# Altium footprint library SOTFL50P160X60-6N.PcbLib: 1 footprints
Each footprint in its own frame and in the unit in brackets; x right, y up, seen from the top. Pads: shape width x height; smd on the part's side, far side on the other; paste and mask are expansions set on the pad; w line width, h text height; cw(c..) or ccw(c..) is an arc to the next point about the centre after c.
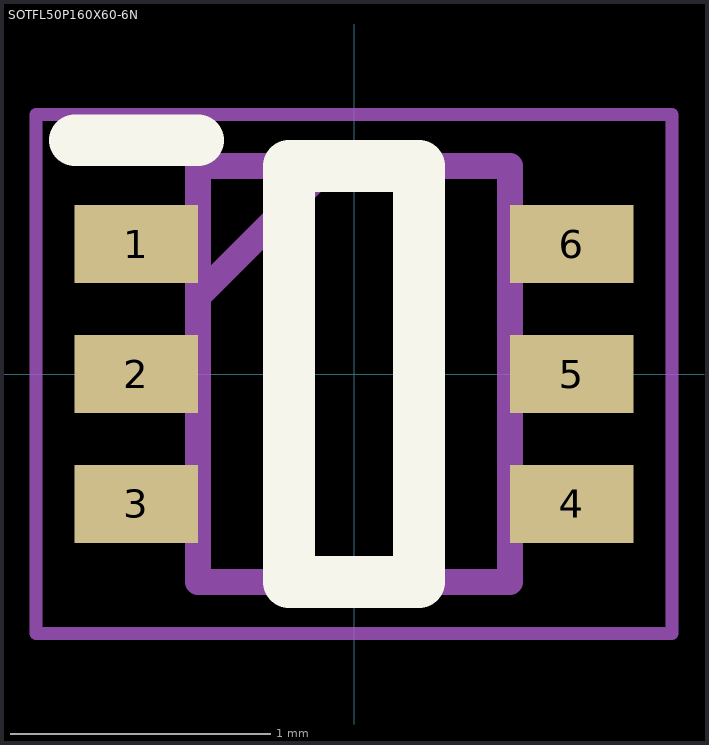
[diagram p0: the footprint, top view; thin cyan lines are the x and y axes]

## SOTFL50P160X60-6N [mm]
pads (6):
  rect 0.475x0.3 smd: 1(-0.838,0.5) 2(-0.838,0) 3(-0.838,-0.5) 4(0.838,-0.5) 5(0.838,0) 6(0.838,0.5)
Top Overlay:
  lines w0.2: -1.075,0.9 -0.6,0.9 ; -0.25,-0.8 0.25,-0.8 0.25,0.8 -0.25,0.8 -0.25,-0.8
Mechanical 15:
  lines w0.1: -0.6,0.3 -0.1,0.8 ; -0.6,-0.8 0.6,-0.8 0.6,0.8 -0.6,0.8 -0.6,-0.8
Mechanical 20:
  lines w0.05: -1.225,-1 1.225,-1 1.225,1 -1.225,1 -1.225,-1
3D body "DRV8210DRLR.stp": height 5.8, standoff -4.65, extent -10,-3.376 10,3.376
